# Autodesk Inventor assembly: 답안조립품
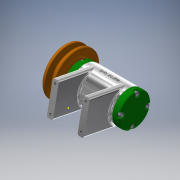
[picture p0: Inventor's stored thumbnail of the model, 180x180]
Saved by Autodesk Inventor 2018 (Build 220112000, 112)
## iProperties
Created: 2020-07
Part Number: 답안조립품
Material: 일반
Document SubType Name: Assembly
Designer: home
Author: home
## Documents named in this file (14)
- C:\Users\home\Desktop\700706V1030\답안조립품.iam
- C:\Users\home\Desktop\700706V1030\베어링 6002.ipt
- C:\Users\home\Desktop\700706V1030\본체.ipt
- C:\Users\home\Desktop\700706V1030\뒤커버.ipt
- C:\Users\home\Desktop\700706V1030\앞커버.ipt
- C:\Users\home\Desktop\700706V1030\축.ipt
- C:\Users\home\Desktop\700706V1030\오일 실 15 25 7.ipt
- C:\Users\home\Desktop\700706V1030\키 3x3x12.ipt
- C:\Users\home\Desktop\700706V1030\V벨트풀리.ipt
- C:\Users\home\Desktop\700706V1030\와셔 6x11.5.ipt
- C:\Users\home\Desktop\700706V1030\스프링와셔 8.ipt
- C:\Users\home\Desktop\700706V1030\너트 M8.ipt
- C:\Users\home\Desktop\700706V1030\볼트 M6x8.ipt
- C:\Users\home\Desktop\700706V1030\볼트 M4x12.ipt
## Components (1 placed, 1 different names)
1. V벨트풀리:1
